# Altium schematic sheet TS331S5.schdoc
size 127 x 101 mm
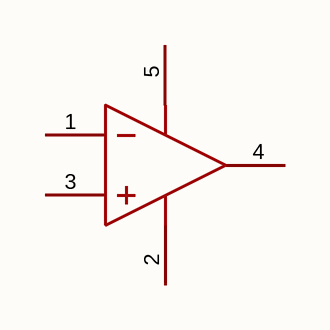
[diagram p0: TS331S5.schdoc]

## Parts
U?  ts331s5  [SOT-23-5_L3.0-W1.7-P0.95-LS2.8-BR]  (value not drawn)

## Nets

Not connected (* = marked no-connect by the designer): U? 1(-IN) 2(V-) 3(+IN) 4(OUT) 5(V+)

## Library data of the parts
U? = ts331s5: 比较器数:单路;输入失调电压(Vos):2mV;输入偏置电流(Ib):25nA;; Manufacturer: TECH PUBLIC(台舟); AddInBom: yes; ModelId: 0a2a1b8f50944f73965918ad6e5fe167; ModelName: SOT-23-5_L2.9-W1.6-H1.1-LS2.8-P0.95; ModelTransform: 114.173,109.636,0,180,0,0,0,0,0; Number of Channels: 单路; Vos - Input Offset Voltage: 2mV; Ib - Input Bias Current: 25nA; Output Mode: MOS；CMOS；ECL；DTL；TTL; Quiescent Current: 400uA; Maximum Power Supply Range (Vdd-Vss): 36V; Single Supply: 2V~36V; Dual Supply: -18V~-1V；1V~18V; Input Offset Current(Ios): 0.5nA; Response Time (tr): 1.3us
